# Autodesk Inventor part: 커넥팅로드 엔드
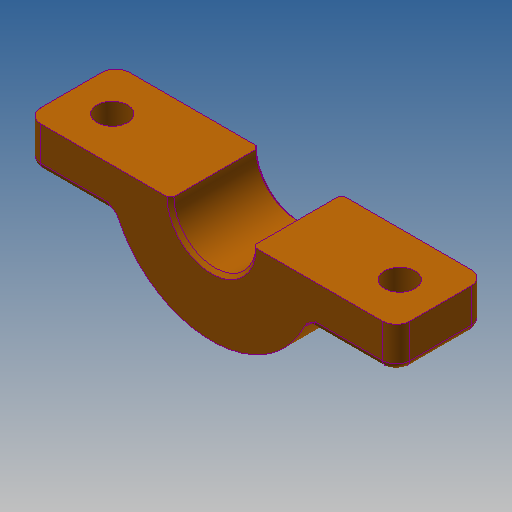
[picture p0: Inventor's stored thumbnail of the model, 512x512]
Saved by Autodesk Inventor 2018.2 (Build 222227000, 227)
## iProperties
Created: 2016-11
Part Number: 커넥팅로드 엔드
Material: 알루미늄 6061
Document SubType Name: Modeling
Designer: mduedu
Density: 2.71 g/cm^3
Mass: 15.0819 g
Surface Area: 26.6719 cm^2
Volume: 5.56529 cm^3
Appearance: 주황색
Author: mduedu
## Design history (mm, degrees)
sketch "스케치1" dims "d0" = 30, "d3" = 15
  geometry: L1 (0, 0)-(0, 96); L2 (-5, 90.41)-(-10, 11.18); L3 (5, 90.41)-(10, 11.18); C1 r 6 at (0, 0); C2 r 4 at (0, 96); 3 further points
  constraints: 6 end point, 4 coincident, 2 centre point, 2 symmetric about line, 1 vertical, 6 other
  dimensions: "d1" = 12 diameter of C1; "d2" = 8 diameter of C2; "d4" = 96 distance of L1.start L1.end; "d6" = 10 distance from line of L1 L2.end; "d7" = 5 distance from line of L1 L2.start
extrude "돌출1" new body sketch "스케치1" stored distance "d8" = 13; taper "d9" = 0 deg
extrude "돌출2" join sketch "스케치1" stored distance "d10" = 32; taper "d11" = 0 deg
sketch "스케치2"
  geometry: L1 (5, 90.41)-(10, 11.18) reference; L2 (-5, 90.41)-(-10, 11.18) reference; A1 r 7.5 centre (0, 96) between (5, 90.41) and (-5, 90.41) reference; A2 r 15 centre (0, 0) between (10, 11.18) and (-10, 11.18) reference
extrude "돌출3" join sketch "스케치2" stored distance "d12" = 8; taper "d13" = 0 deg
sketch "스케치3"
  geometry: L1 (-2.732, 78.715)-(-6.171, 24.226); L2 (2.732, 78.715)-(6.171, 24.226); L3 (0, 78.5)-(0, 25); A1 r 17.5 centre (0, 96) between (-2.732, 78.715) and (2.732, 78.715); A2 r 25 centre (0, 0) between (6.171, 24.226) and (-6.171, 24.226); 9 further points; 2 other entities
  constraints: 6 end point, 6 point on circle, 2 centre point, 1 symmetric about line, 1 vertical alignment, 6 other
  dimensions: "d18" = 10 dimension on A1; "d19" = 10 dimension on A2; "d20" = 3 dimension on L1
extrude "돌출4" cut sketch "스케치3" distance "d21" = 2; taper "d22" = 0 deg
fillet "모깎기1" dims "d23" = 2
fillet "모깎기2" dims "d24" = 2
fillet "모깎기3" dims "d25" = 1
chamfer "모따기1" distance "d26" = 0.5; stored, may be unused: second distance "d27" = 2, angle "d28" = 45 deg
sketch "스케치4"
  geometry: L1 (-27, -6)-(-13.748, -6); L2 (27, -6)-(27, 6); L3 (27, 6)-(13.748, 6); L4 (-27, 6)-(-27, -6); L5 (-27, -6)-(27, 6); L6 (27, -6)-(-27, 6); L7 (-13.748, 6)-(-27, 6); L8 (13.748, 6)-(-13.748, 6); L9 (13.748, -6)-(27, -6); L10 (-13.748, -6)-(13.748, -6); A1 r 15 centre (0, 0) between (-13.748, 6) and (13.748, 6) reference; 1 further point
  constraints: 20 end point, 10 parallel, 4 point on circle, 3 horizontal, 3 perpendicular, 2 midpoint
  dimensions: "d29" = 54 distance of L1.start L2.start; "d31" = 12 distance of L2.start L2.end
extrude "돌출5" join sketch "스케치4" stored distance "d32" = 0; taper "d33" = 0 deg
fillet "모깎기4" dims "d34" = 2
fillet "모깎기5" dims "d35" = 1
fillet "모깎기6" dims "d36" = 1
sketch "스케치5"
  geometry: L1 (1, 0)-(1, 9) reference; L2 (-18.5, 20.5)-(-33.5, 20.5) reference; L3 (-33.5, -11.5)-(-18.5, -11.5) reference; L4 (-26, 20.5)-(-26, -11.5); 3 further points
  constraints: 2 end point, 2 midpoint, 1 horizontal alignment, 1 symmetric about line
  dimensions: "d37" = 6 distance from line of point (-5, 4.5) L1
feature "분할1"
sketch "스케치7"
  geometry: 2 further points
  constraints: 2 other
hole "구멍2" sketch "스케치7" at (-47, 4.5), (-5, 4.5) diameter "d45" = 4.5; stored, may be unused: countersink angle "d49" = 90 deg, drill point angle "d51" = 0 deg; dims "d46" = 6, "d47" = 4, "d48" = 2, "d50" = 8
node "솔리드1"
mirror "대칭1"
other parameters: "d16" = 4, "d17" = 4
